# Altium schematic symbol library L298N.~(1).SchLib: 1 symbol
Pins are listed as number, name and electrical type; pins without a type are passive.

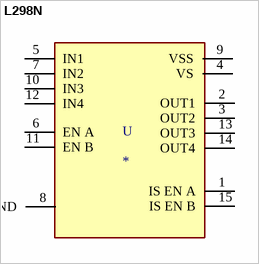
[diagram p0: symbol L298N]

## L298N
designator U
Half Bridge _4_ Driver DC Motors, Relays, Solenoids, Stepper Motors Bipolar 15-Multiwatt; MP: L298N; MF: STMicroelectronics
footprint TO127P2020X500X2100-15
pins: 1 IS EN A, 2 OUT1 (hiz), 3 OUT2 (hiz), 4 VS (power), 5 IN1 (hiz), 6 EN A (hiz), 7 IN2 (hiz), 8 GND (power), 9 VSS (hiz), 10 IN3 (hiz), 11 EN B (hiz), 12 IN4 (hiz), 13 OUT3 (hiz), 14 OUT4 (hiz), 15 IS EN B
